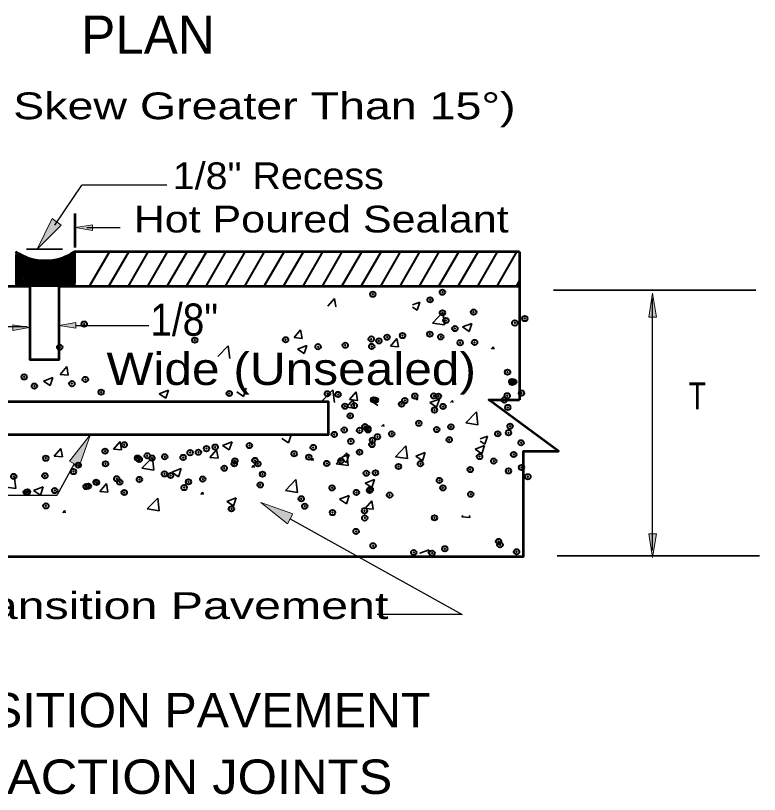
# Model space of a CAD drawing. Extents: x 36.4 to 71.7, y 0.5 to 22.5.
# Drawn here: x 55.288 to 59.178, y 12.776 to 16.85 of the extents above; entities that cross this region are included whole.
import ezdxf

# ---------------------------------------------------------------- set-up
doc = ezdxf.new("R2010")
doc.units = 0
doc.header["$LTSCALE"] = 0.056
doc.header["$PDMODE"] = 32
doc.header["$PDSIZE"] = 0.028
for name, color, linetype, lineweight in [('1', 7, 'Continuous', 40), ('3', 7, 'Continuous', 13), ('6', 7, 'Continuous', 13)]:
    doc.layers.add(name, color=color, linetype=linetype, lineweight=lineweight)

msp = doc.modelspace()

# ---------------------------------------------------------------- hatches: boundary and pattern name
at = {"layer": '1'}
for points in [[(58.64033, 15.2725), (58.59867, 15.2725), (58.6195, 15.3975), (58.6195, 15.3975)], [(58.64033, 14.14), (58.59867, 14.14), (58.6195, 14.015), (58.6195, 14.015)]]:
    msp.add_hatch(color=256, dxfattribs=at).paths.add_polyline_path(points)
at = {"layer": '3'}
for points in [[(55.52717, 15.75475), (55.47958, 15.78892), (55.40083, 15.62917), (55.40083, 15.62917)], [(55.69017, 15.72658), (55.69017, 15.75592), (55.60225, 15.74125), (55.60225, 15.74125)], [(55.60392, 15.21483), (55.60392, 15.24417), (55.516, 15.2295), (55.516, 15.2295)], [(55.27283, 15.23242), (55.27283, 15.20317), (55.36075, 15.21775), (55.36075, 15.21775)], [(55.56942, 14.51908), (55.62083, 14.49075), (55.68033, 14.65867), (55.68033, 14.65867)], [(56.70992, 14.19183), (56.73842, 14.24308), (56.57058, 14.30283), (56.57058, 14.30283)]]:
    msp.add_hatch(color=256, dxfattribs=at).paths.add_polyline_path(points)

# ---------------------------------------------------------------- linework, layer by layer
at = {"layer": '1', "lineweight": 53}
for p, q in [((55.598, 15.81458), (55.598, 15.63742)), ((55.2975, 15.60733), (55.29792, 15.60733)), ((55.59675, 15.60508), (55.58367, 15.60508)), ((55.5965, 15.60717), (55.58608, 15.60717)), ((55.59617, 15.60833), (55.591, 15.60833)), ((55.59617, 15.61183), (55.59308, 15.61183)), ((55.5965, 15.61183), (55.59517, 15.61183)), ((55.59708, 15.61275), (55.59575, 15.61275)), ((55.59725, 15.45108), (55.59725, 15.61458)), ((57.9235, 15.61458), (55.59725, 15.61458)), ((57.9235, 15.61458), (57.9235, 14.84025)), ((55.41975, 15.56608), (55.28833, 15.56608)), ((55.30408, 15.59858), (55.30567, 15.59858)), ((55.31283, 15.58983), (55.313, 15.58983)), ((55.595, 15.56608), (55.46608, 15.56608)), ((55.595, 15.56817), (55.48458, 15.56817)), ((55.595, 15.57133), (55.50125, 15.57133)), ((55.595, 15.57517), (55.51592, 15.57517)), ((55.59592, 15.57783), (55.52625, 15.57783)), ((55.59708, 15.58283), (55.54025, 15.58283)), ((55.59533, 15.586), (55.54825, 15.586)), ((55.59533, 15.58925), (55.55583, 15.58925)), ((55.595, 15.5925), (55.56167, 15.5925)), ((55.59675, 15.59517), (55.56725, 15.59517)), ((55.59675, 15.5975), (55.572, 15.5975)), ((55.59675, 15.60067), (55.57783, 15.60067)), ((55.59675, 15.60217), (55.57992, 15.60217)), ((55.54717, 15.557), (55.342, 15.557)), ((52.95075, 15.435), (55.36242, 15.435)), ((55.516, 15.435), (57.9235, 15.435))]:
    msp.add_line(p, q, dxfattribs=at)
at = {"layer": '1', "lineweight": 35}
for p, q in [((55.29883, 15.60758), (55.28817, 15.60758)), ((55.53267, 15.62758), (55.34583, 15.62758)), ((55.33033, 15.478), (55.3305, 15.57408)), ((55.53483, 15.57033), (55.348, 15.57033)), ((59.15883, 15.41325), (58.10042, 15.41325)), ((56.92158, 15.32992), (56.95542, 15.37033)), ((56.9635, 15.32625), (56.95542, 15.37033)), ((57.36333, 15.337), (57.40167, 15.35158)), ((57.36333, 15.32533), (57.38742, 15.30925)), ((57.38742, 15.30925), (57.40167, 15.35158)), ((57.46825, 15.24192), (57.523, 15.29908)), ((57.53083, 15.23217), (57.523, 15.29908)), ((57.46825, 15.24192), (57.53067, 15.23217)), ((57.62458, 15.22142), (57.67383, 15.24033)), ((57.6595, 15.19783), (57.67383, 15.24033)), ((56.74442, 15.16558), (56.77825, 15.20592)), ((56.7865, 15.16183), (56.77825, 15.20592)), ((57.62458, 15.22142), (57.6595, 15.19783)), ((56.74442, 15.16558), (56.78633, 15.16183)), ((57.24867, 15.12142), (57.28258, 15.16183)), ((57.29067, 15.11767), (57.28258, 15.16183)), ((56.34525, 15.06658), (56.40008, 15.12358)), ((56.40783, 15.05683), (56.40008, 15.12358)), ((56.76167, 15.106), (56.81083, 15.12483)), ((56.79658, 15.08242), (56.811, 15.12483)), ((57.24867, 15.12142), (57.29067, 15.11767)), ((57.777, 15.10592), (57.78692, 15.11767)), ((57.78917, 15.10592), (57.78692, 15.11767)), ((56.76167, 15.106), (56.79658, 15.08242)), ((55.52192, 14.97342), (55.55575, 15.01392)), ((55.56383, 14.96983), (55.55575, 15.01392)), ((55.434, 14.93833), (55.48317, 14.95717)), ((55.46892, 14.91475), (55.48317, 14.95717)), ((55.52192, 14.97342), (55.56383, 14.96983)), ((55.434, 14.93833), (55.46892, 14.91475)), ((56.03883, 14.87192), (56.08808, 14.89075)), ((56.03883, 14.87192), (56.07375, 14.84833)), ((56.07375, 14.84833), (56.08808, 14.89075)), ((56.4445, 14.88208), (56.4795, 14.85842)), ((56.4795, 14.85842), (56.49375, 14.90092)), ((56.893, 14.83608), (56.94775, 14.89317)), ((56.9555, 14.82642), (56.94775, 14.89317)), ((57.03475, 14.84117), (57.06875, 14.88142)), ((57.01908, 14.80108), (57.05292, 14.84158)), ((57.06117, 14.79742), (57.05292, 14.84158)), ((57.15375, 14.83033), (57.18183, 14.84117)), ((57.15375, 14.83033), (57.18183, 14.81142)), ((57.38425, 14.83825), (57.39233, 14.84658)), ((57.45492, 14.82567), (57.50417, 14.84458)), ((57.48992, 14.80217), (57.50425, 14.84458)), ((57.563, 14.82558), (57.57308, 14.83742)), ((57.57525, 14.82558), (57.57308, 14.83742)), ((57.01908, 14.80108), (57.06117, 14.79742)), ((57.45492, 14.82567), (57.48992, 14.80217)), ((57.64333, 14.71975), (57.69825, 14.77683)), ((57.70592, 14.71), (57.69825, 14.77683)), ((57.20158, 14.7), (57.21167, 14.71183)), ((57.21383, 14.7), (57.21167, 14.71183)), ((57.64333, 14.71975), (57.70592, 14.71)), ((56.68058, 14.6385), (56.71542, 14.61483)), ((56.71542, 14.61483), (56.72975, 14.65742)), ((57.71742, 14.63608), (57.75567, 14.65075)), ((57.74142, 14.60833), (57.75567, 14.65075)), ((55.49058, 14.54575), (55.52442, 14.58617)), ((55.53267, 14.54208), (55.52442, 14.58617)), ((55.80033, 14.58267), (55.83417, 14.62308)), ((55.84242, 14.57908), (55.83417, 14.62308)), ((56.37083, 14.60158), (56.42, 14.62042)), ((56.37083, 14.60158), (56.40567, 14.578)), ((56.40567, 14.578), (56.42, 14.62042)), ((57.27458, 14.54267), (57.32942, 14.59975)), ((57.33708, 14.533), (57.32942, 14.59975)), ((57.69092, 14.58217), (57.74008, 14.601)), ((57.71742, 14.6245), (57.74142, 14.60833)), ((57.726, 14.55858), (57.74025, 14.601)), ((55.49058, 14.54575), (55.53258, 14.54208)), ((55.80033, 14.58267), (55.84225, 14.57908)), ((56.30458, 14.53858), (56.33858, 14.57892)), ((56.34658, 14.53483), (56.33858, 14.57892)), ((56.96483, 14.50575), (57.01967, 14.56275)), ((56.99475, 14.54008), (57.03308, 14.55475)), ((57.01875, 14.51233), (57.03308, 14.55475)), ((57.02742, 14.496), (57.01967, 14.56275)), ((57.38117, 14.54533), (57.43033, 14.56408)), ((57.38117, 14.54533), (57.41625, 14.52175)), ((57.41625, 14.52175), (57.43058, 14.56408)), ((57.69092, 14.58217), (57.726, 14.55858)), ((55.94892, 14.482), (56.00367, 14.53908)), ((56.0115, 14.47225), (56.00367, 14.53908)), ((56.30458, 14.53858), (56.34658, 14.53483)), ((56.83292, 14.52292), (56.84283, 14.53483)), ((56.84508, 14.52292), (56.84283, 14.53483)), ((56.96483, 14.50575), (57.02742, 14.496)), ((56.99475, 14.5285), (57.01875, 14.51233)), ((57.27458, 14.54267), (57.33708, 14.533)), ((55.94892, 14.482), (56.01133, 14.47225)), ((56.10525, 14.46142), (56.15442, 14.48025)), ((56.14017, 14.43783), (56.15442, 14.48025)), ((56.52317, 14.48608), (56.53308, 14.49792)), ((56.53533, 14.48608), (56.53308, 14.49792)), ((55.28883, 14.37625), (55.281, 14.44308)), ((56.10525, 14.46142), (56.14017, 14.43783)), ((56.69933, 14.36567), (56.75417, 14.42267)), ((56.76183, 14.35592), (56.75417, 14.42267)), ((57.11567, 14.40508), (57.16483, 14.42392)), ((57.15075, 14.38158), (57.165, 14.42392)), ((55.22625, 14.386), (55.28867, 14.37625)), ((55.38258, 14.36542), (55.43183, 14.38442)), ((55.4175, 14.34183), (55.43183, 14.38442)), ((55.72925, 14.36158), (55.76333, 14.40183)), ((55.77133, 14.35783), (55.76333, 14.40183)), ((57.11567, 14.40508), (57.15075, 14.38158)), ((55.38258, 14.36542), (55.4175, 14.34183)), ((55.72925, 14.36158), (55.77133, 14.35783)), ((56.25758, 14.34592), (56.26758, 14.35783)), ((56.26975, 14.34592), (56.26758, 14.35783)), ((56.69933, 14.36567), (56.76183, 14.35592)), ((55.97658, 14.26967), (56.03142, 14.32675)), ((56.03908, 14.25992), (56.03142, 14.32675)), ((56.39292, 14.30908), (56.44217, 14.32792)), ((56.39292, 14.30908), (56.428, 14.28558)), ((56.428, 14.28558), (56.44225, 14.32792)), ((56.98258, 14.32042), (57.03183, 14.33942)), ((56.98258, 14.32042), (57.01767, 14.29692)), ((57.01767, 14.29692), (57.03183, 14.33942)), ((57.11667, 14.27217), (57.1505, 14.31267)), ((57.15867, 14.26858), (57.1505, 14.31267)), ((55.53492, 14.24992), (55.54483, 14.26183)), ((55.54708, 14.24992), (55.54483, 14.26183)), ((55.97658, 14.26967), (56.03908, 14.25992)), ((57.11667, 14.27217), (57.15867, 14.26858)), ((57.621, 14.22808), (57.62758, 14.23608)), ((57.40242, 14.03733), (57.45167, 14.05633)), ((57.44483, 14.03608), (57.45167, 14.05633)), ((57.40242, 14.03733), (57.40442, 14.03608)), ((59.17783, 14.02458), (58.11942, 14.02458))]:
    msp.add_line(p, q, dxfattribs=at)
at = {"layer": '1', "lineweight": 60}
for p, q in [((55.30333, 15.60458), (55.28817, 15.60458)), ((55.30892, 15.601), (55.28817, 15.601)), ((55.31908, 15.59575), (55.28817, 15.59575)), ((55.32617, 15.59008), (55.28817, 15.59008)), ((55.34858, 15.58075), (55.28817, 15.58075)), ((55.35992, 15.57633), (55.28817, 15.57633)), ((55.37817, 15.5725), (55.28817, 15.5725)), ((55.32383, 15.59342), (55.28825, 15.59342)), ((55.3135, 15.59833), (55.28833, 15.59833)), ((55.39067, 15.56825), (55.28833, 15.56825)), ((55.34575, 15.57858), (55.2885, 15.57858)), ((55.37683, 15.56992), (55.2885, 15.56992)), ((55.33458, 15.587), (55.28858, 15.587)), ((55.368, 15.57367), (55.28858, 15.57367)), ((55.33967, 15.58358), (55.28867, 15.58358))]:
    msp.add_line(p, q, dxfattribs=at)
at = {"layer": '1'}
for p, q in [((55.67492, 15.435), (55.77867, 15.61458)), ((55.77642, 15.435), (55.88008, 15.61458)), ((55.87783, 15.435), (55.98167, 15.61458)), ((55.97942, 15.435), (56.08308, 15.61458)), ((56.081, 15.435), (56.18458, 15.61458)), ((56.1825, 15.435), (56.28608, 15.61458)), ((56.284, 15.435), (56.38758, 15.61458)), ((56.38542, 15.435), (56.489, 15.61458)), ((56.487, 15.435), (56.59058, 15.61458)), ((56.58842, 15.435), (56.692, 15.61458)), ((56.68992, 15.435), (56.7935, 15.61458)), ((56.79133, 15.435), (56.895, 15.61458)), ((56.89292, 15.435), (56.9965, 15.61458)), ((56.99433, 15.435), (57.09792, 15.61458)), ((57.09583, 15.435), (57.1995, 15.61458)), ((57.19733, 15.435), (57.30092, 15.61458)), ((57.29883, 15.435), (57.40242, 15.61458)), ((57.40025, 15.435), (57.50383, 15.61458)), ((57.50183, 15.435), (57.60542, 15.61458)), ((57.60325, 15.435), (57.70683, 15.61458)), ((57.70475, 15.435), (57.80833, 15.61458)), ((57.80625, 15.435), (57.90983, 15.61458)), ((57.90775, 15.435), (57.9235, 15.46258))]:
    msp.add_line(p, q, dxfattribs=at)
at = {"layer": '1', "lineweight": 25}
msp.add_line((58.61867, 14.05383), (58.61867, 15.37025), dxfattribs=at)
at = {"layer": '1', "lineweight": 53}
for points in [[(52.95075, 15.61458), (52.95075, 14.829), (52.82233, 14.829), (53.12183, 14.54867), (52.972, 14.54867), (52.972, 14.02125), (57.945, 14.02125), (57.945, 14.571), (58.12675, 14.571), (57.76308, 14.84025), (57.9235, 14.84025)], [(55.29092, 15.4385), (55.59558, 15.4385), (55.59625, 15.60742), (55.59667, 15.61192)], [(55.58683, 15.60258), (55.58683, 15.44508), (55.2975, 15.44508), (55.2975, 15.60733)], [(55.58025, 15.59358), (55.58025, 15.45167), (55.30408, 15.45167), (55.30433, 15.60433)], [(55.29225, 15.60275), (55.29192, 15.59842), (55.29092, 15.4385)], [(55.57367, 15.58458), (55.57367, 15.46267), (55.31283, 15.46267), (55.31283, 15.58983)], [(55.322, 15.57883), (55.32158, 15.57883), (55.32158, 15.46925)], [(55.32158, 15.46925), (55.56708, 15.46925), (55.56708, 15.57558)], [(55.33033, 15.478), (55.5605, 15.478), (55.5605, 15.57292)], [(55.42208, 15.56492), (55.33833, 15.56492), (55.33833, 15.486), (55.55308, 15.486), (55.55308, 15.56492), (55.46408, 15.56492)], [(55.36242, 15.435), (55.36242, 15.05125), (55.516, 15.05125), (55.516, 15.435)]]:
    msp.add_lwpolyline(points, dxfattribs=at)
for points in [[(55.33917, 15.48458), (55.55392, 15.48458), (55.55392, 15.5635), (55.33917, 15.5635)], [(55.34575, 15.489), (55.54517, 15.489), (55.54517, 15.55258), (55.34575, 15.55258)], [(55.3545, 15.49775), (55.54083, 15.49775), (55.54083, 15.55033), (55.3545, 15.55033)], [(55.36325, 15.5065), (55.532, 15.5065), (55.532, 15.54158), (55.36325, 15.54158)], [(55.36983, 15.51308), (55.532, 15.51308), (55.532, 15.53067), (55.36983, 15.53067)], [(55.37858, 15.51525), (55.52767, 15.51525), (55.52767, 15.52183), (55.37858, 15.52183)], [(53.96333, 14.65867), (56.92392, 14.65867), (56.92392, 14.82925), (53.96333, 14.82925)]]:
    msp.add_lwpolyline(points, close=True, dxfattribs=at)
at = {"layer": '1', "lineweight": 13}
for points in [[(58.64033, 15.2725), (58.59867, 15.2725), (58.6195, 15.3975), (58.6195, 15.3975)], [(58.64033, 14.14), (58.59867, 14.14), (58.6195, 14.015), (58.6195, 14.015)]]:
    msp.add_lwpolyline(points, close=True, dxfattribs=at)
at = {"layer": '1', "lineweight": 35}
for points in [[(57.03475, 14.84117), (57.07683, 14.83742), (57.06875, 14.88142)], [(57.621, 14.22808), (57.66308, 14.22433), (57.66092, 14.23608)]]:
    msp.add_lwpolyline(points, dxfattribs=at)
at = {"layer": '1', "lineweight": 60}
msp.add_arc((55.44258, 15.83602), 0.2701, 235.06709, 304.93291, dxfattribs=at)
at = {"layer": '1'}
for p in [(57.15633, 15.39242), (57.52008, 15.40317), (57.45558, 15.36342), (57.52025, 15.29533), (57.6835, 15.29908), (57.95108, 15.26542), (55.647, 15.23625), (57.53867, 15.25517), (57.89858, 15.24217), (57.45458, 15.18367), (57.58583, 15.21283), (56.22542, 15.15225), (56.70008, 15.15467), (57.14792, 15.15842), (57.18833, 15.14867), (57.23067, 15.16783), (57.31158, 15.17658), (57.5115, 15.16917), (55.51875, 15.11533), (56.86967, 15.11833), (57.01225, 15.1255), (57.15042, 15.11958), (57.613, 15.13917), (57.68867, 15.14092), (57.86067, 14.985), (55.333, 14.96017), (55.65283, 14.94733), (55.38658, 14.91225), (55.58292, 14.92483), (57.88258, 14.93625), (57.88483, 14.931), (57.89292, 14.93442), (55.73558, 14.88033), (56.40567, 14.87342), (56.91867, 14.872), (56.9745, 14.86833), (57.37583, 14.85967), (57.47483, 14.86067), (57.49925, 14.85958), (57.859, 14.86158), (57.93358, 14.87592), (57.15992, 14.84025), (57.17025, 14.83842), (57.30692, 14.81758), (57.32333, 14.83633), (57.84375, 14.83933), (57.01058, 14.80692), (57.059, 14.80983), (57.47858, 14.78658), (57.5235, 14.80558), (57.86225, 14.80033), (57.0385, 14.75642), (57.11483, 14.70033), (57.39692, 14.7175), (57.56483, 14.69892), (57.87408, 14.70225), (56.9545, 14.65933), (57.007, 14.68258), (57.08717, 14.68067), (57.13058, 14.68258), (57.13075, 14.69017), (57.25508, 14.662), (57.49017, 14.6845), (57.80958, 14.6625), (57.86558, 14.6685), (57.0415, 14.62317), (57.15467, 14.62842), (57.18042, 14.6475), (57.55583, 14.63158), (57.93117, 14.61583), (55.756, 14.57167), (55.85633, 14.60517), (56.28658, 14.58483), (56.332, 14.593), (56.5105, 14.60083), (56.84492, 14.59158), (57.15133, 14.60625), (55.44633, 14.53483), (55.92558, 14.53542), (55.977, 14.548), (56.001, 14.53542), (56.06817, 14.5425), (56.16417, 14.53908), (56.20075, 14.56392), (56.24425, 14.56575), (56.74458, 14.55808), (56.82167, 14.5405), (57.087, 14.5665), (57.71458, 14.54308), (57.89275, 14.55433), (55.61583, 14.4985), (55.7585, 14.50558), (55.9345, 14.52883), (56.43175, 14.50558), (56.43492, 14.52108), (56.53958, 14.52325), (56.55525, 14.50542), (56.91492, 14.50742), (56.98958, 14.52183), (57.29025, 14.49142), (57.40483, 14.50608), (57.7885, 14.51992), (55.59083, 14.46508), (56.0665, 14.45283), (56.37925, 14.48217), (56.57942, 14.45142), (57.12225, 14.45617), (57.17, 14.45833), (57.66558, 14.47558), (57.86558, 14.46825), (57.93358, 14.48625), (55.27825, 14.43942), (55.4415, 14.44308), (55.709, 14.40958), (55.81683, 14.42725), (55.83258, 14.40942), (55.93525, 14.42383), (56.09892, 14.4445), (56.19225, 14.41142), (56.26683, 14.42583), (57.50442, 14.41867), (57.967, 14.43825), (55.6565, 14.38633), (55.669, 14.38867), (55.71133, 14.40783), (56.16933, 14.38092), (56.56758, 14.39542), (56.94283, 14.37967), (57.14283, 14.37225), (57.523, 14.37975), (55.34375, 14.35683), (55.35033, 14.35833), (55.49292, 14.36542), (55.85667, 14.35542), (57.07033, 14.35608), (57.13925, 14.36592), (57.24425, 14.34225), (57.668, 14.34617), (56.78183, 14.32267), (55.44658, 14.28508), (56.41667, 14.27008), (56.80025, 14.28375), (56.94542, 14.25017), (57.11258, 14.26033), (57.11367, 14.22217), (57.47858, 14.22283), (57.0685, 14.15233), (57.81408, 14.09958), (57.82125, 14.08258), (57.15758, 14.07733), (57.53292, 14.06142), (57.90833, 14.04558), (57.36992, 14.04108), (57.466, 14.03758)]:
    msp.add_point(p, dxfattribs=at)
at = {"layer": '3', "lineweight": 25}
for p, q in [((55.49317, 15.75433), (55.63383, 15.96325)), ((56.079, 15.96325), (55.63383, 15.96325)), ((55.66017, 15.74225), (55.8355, 15.74225)), ((55.349, 15.22217), (55.02717, 15.22217)), ((55.60392, 15.2295), (55.98442, 15.2295))]:
    msp.add_line(p, q, dxfattribs=at)
at = {"layer": '3'}
for points in [[(55.52717, 15.75475), (55.47958, 15.78892), (55.40083, 15.62917), (55.40083, 15.62917)], [(55.69017, 15.72658), (55.69017, 15.75592), (55.60225, 15.74125), (55.60225, 15.74125)], [(55.60392, 15.21483), (55.60392, 15.24417), (55.516, 15.2295), (55.516, 15.2295)], [(55.27283, 15.23242), (55.27283, 15.20317), (55.36075, 15.21775), (55.36075, 15.21775)], [(55.56942, 14.51908), (55.62083, 14.49075), (55.68033, 14.65867), (55.68033, 14.65867)], [(56.70992, 14.19183), (56.73842, 14.24308), (56.57058, 14.30283), (56.57058, 14.30283)]]:
    msp.add_lwpolyline(points, close=True, dxfattribs=at)
at = {"layer": '3', "lineweight": 25}
for points in [[(55.59508, 14.50492), (55.50375, 14.33992), (54.99492, 14.33992)], [(56.72425, 14.21733), (57.62342, 13.71717), (57.17817, 13.71717)]]:
    msp.add_lwpolyline(points, dxfattribs=at)
at = {"layer": '6', "lineweight": 25}
msp.add_line((55.36242, 15.05125), (55.3625, 15.05125), dxfattribs=at)

# ---------------------------------------------------------------- texts
at = {"layer": '3'}
msp.add_text('PLAN', height=0.2, dxfattribs=at).set_placement((55.63117, 16.65025))
for s, height, width, p in [('(Bridge Skew Greater Than 15°)', 0.14, 1.3, (54.42342, 16.30808)), ('1/8" Recess', 0.14, 1.1, (56.11033, 15.94233)), ('Hot Poured Sealant', 0.14, 1.2, (55.90583, 15.71575)), ('1/8"', 0.1687, 0.9, (55.9925, 15.17533)), ('Wide (Unsealed)', 0.1687, 1.15, (55.76367, 14.91808)), ('T', 0.14, 0.8, (58.80758, 14.79142)), ('Bridge Transition Pavement', 0.14, 1.35, (54.11892, 13.69375)), ('BRIDGE TRANSITION PAVEMENT', 0.18, 1.05, (53.42692, 13.12717)), ('CONTRACTION JOINTS', 0.18, 1.1, (54.30158, 12.77875))]:
    msp.add_text(s, height=height, dxfattribs=dict(at, width=width)).set_placement(p)

doc.saveas('drawing.dxf')
